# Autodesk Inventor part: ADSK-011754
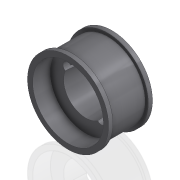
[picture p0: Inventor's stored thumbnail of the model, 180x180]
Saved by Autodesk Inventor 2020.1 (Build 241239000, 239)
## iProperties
Created: 1999-11
Part Number: ADSK-011754
Material: Acier (alliage faible hypertrempé)
Description: SPROCKET,TIMING,TL,0.50P,20T,USE BUSH 1210
Document SubType Name: Modeling
Designer: dmcquary
Density: 7.84 g/cm^3
Appearance: Metal-Steel(Polish)
Mass: 827.025 g
Surface Area: 318.708 cm^2
Volume: 105.488 cm^3
Control State: 0
Checked Out: False
Last Check In By: sspink
Last Check In Date: 1999-12-22
Master: False
Shininess: 0.0
Length Units: 11269
Angle Units: 11279
Time Units: 11290
Mass Units: 11283
Length Display Precision: 3
Angle Display Precision: 2
Compacted: True
Dimensions: 87,4x87,4x47,2 mm
Mass: 0,827 kg
DocNumber: ADSK-011754.ipt
Folder: 01 - Themengebiete\Simplification\01 - Packaging machine\
VDS_Category: 3D Komponenten
Density: 0.0
Volumn: 0.0
Area: 0.0
PropertySet Name: Model Information
Author: dmcquary
Revision Number: -
Title: SPROCKET,TIMING,TL,0.50P,20T,USE BUSH 1210
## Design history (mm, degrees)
node "Extrusion1" dims "d1" = 25.4, "d2" = 0
node "Extrusion2" dims "d3" = 25.4, "d4" = -4 deg
workaxis "Work Axis3"
node "Extrusion4" dims "d16" = 2.794, "d17" = 0
node "Extrusion5" dims "d20" = 19.05, "d21" = 0
node "Hole2" dims "d26" = 10, "d27" = 9.525, "d28" = 6.35, "d29" = 60 deg, "d30" = 19.05, "d31" = 118 deg, "d56" = 6
node "Hole3" dims "d33" = 8, "d34" = 9.525, "d35" = 6.35, "d36" = 60 deg, "d37" = 19.05, "d38" = 118 deg, "d57" = 6
workplane "Work Plane2"
node "Extrusion6" dims "d44" = 1.778, "d45" = 0
node "Extrusion8" dims "d48" = 16.256, "d49" = 0
node "Extrusion9" dims "d50" = 16.256, "d51" = 0
node "Extrusion10" dims "d52" = 16.256, "d53" = 0
node "Extrusion11" dims "d54" = 1.778, "d55" = 0
workplane "Arbeitsebene3"
node "Solide1"
node "Corps solides"
node "Corps surfaciques"
sketch "Sketch1"
  geometry: C1 r 40.424 at (0, 0)
  constraints: 1 centre point, 1 other
  dimensions: "d0" = 80.8482 diameter of C1
sketch "Sketch2"
  geometry: C1 r 23.812 at (0, 0)
  constraints: 1 centre point, 1 other
  dimensions: "d22" = 47.625 diameter of C1
sketch "Sketch6"
  geometry: C1 r 40.424 at (0, 0) reference; C2 r 38.1 at (0, 0); C3 r 43.688 at (0, 0)
  constraints: 2 centre point, 2 coincident
  dimensions: "d14" = 87.376 diameter of C3; "d15" = 76.2 diameter of C2
sketch "Sketch7"
  geometry: C1 r 38.1 at (0, 0); C2 r 43.688 at (0, 0); 3 further points
  constraints: 2 centre point, 2 coincident, 1 other
  dimensions: "d18" = 87.376 diameter of C2; "d19" = 76.2 diameter of C1
sketch "Sketch8"
  geometry: A1 r 23.812 centre (0, 0) between (-19.531, 13.623) and (16.874, -16.801) reference
  constraints: 2 point on circle
sketch "Sketch10"
  geometry: A1 r 23.812 centre (0, 0) between (20.011, -12.907) and (-16.256, 17.401) reference; 1 further point
  constraints: 1 point on circle
sketch "Sketch12"
  geometry: C1 r 43.688 at (0, 0) reference; C2 r 40.424 at (0, 0) reference
sketch "Sketch14"
  geometry: C1 r 38.1 at (0, 0) reference; C2 r 43.688 at (0, 0) reference
sketch "Sketch15"
  geometry: C1 r 38.1 at (0, 0) reference; C2 r 43.688 at (0, 0) reference
sketch "Sketch16"
  geometry: C1 r 40.424 at (0, 0) reference; C2 r 43.688 at (0, 0) reference
sketch "Sketch17"
  geometry: C1 r 43.688 at (0, 0) reference; C2 r 40.424 at (0, 0) reference
other parameters: "d43" = -23.01875
